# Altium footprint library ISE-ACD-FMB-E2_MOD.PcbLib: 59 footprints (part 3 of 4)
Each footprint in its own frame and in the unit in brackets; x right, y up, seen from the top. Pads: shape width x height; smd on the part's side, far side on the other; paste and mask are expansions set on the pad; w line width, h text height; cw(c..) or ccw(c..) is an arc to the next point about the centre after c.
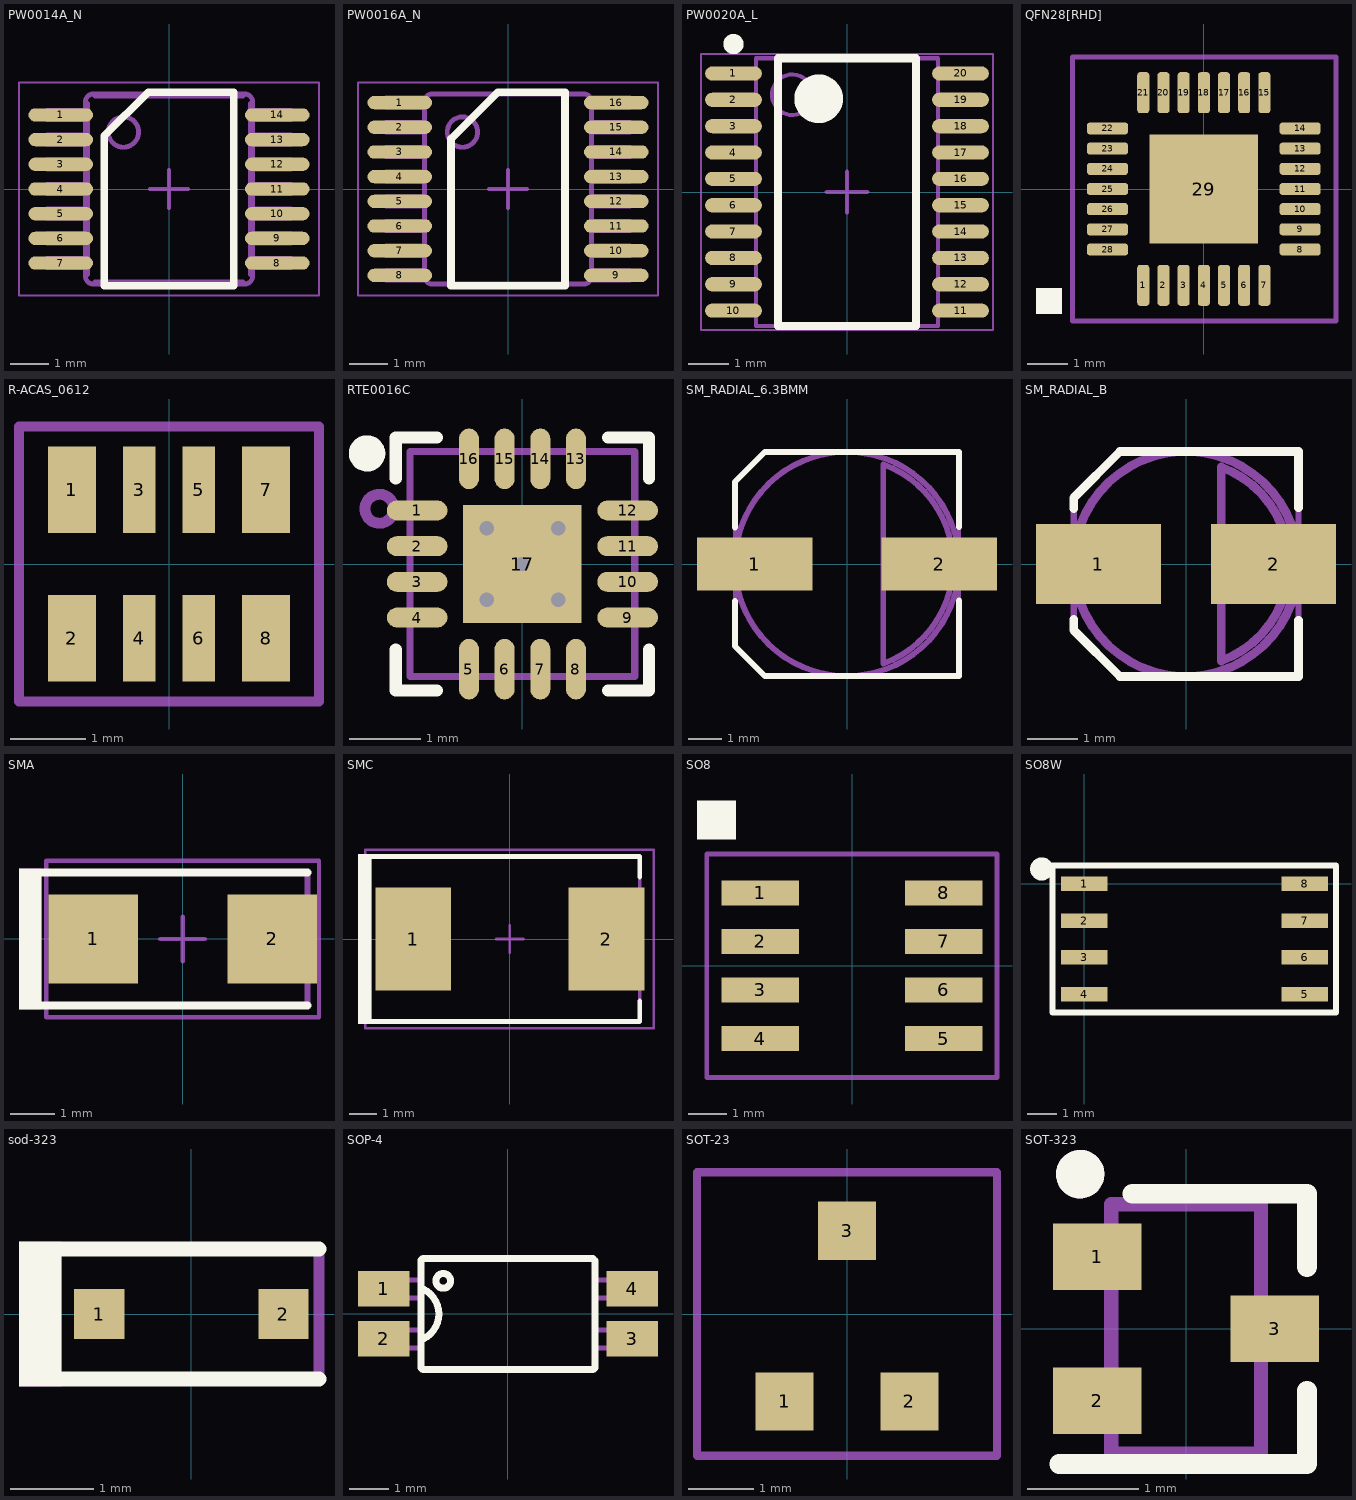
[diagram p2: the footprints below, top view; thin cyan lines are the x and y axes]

## PW0014A_N [mm] "TSOP, 14-Leads, Body 5x4.4mm, Pitch 0.65mm, IPC Medium Density"
height 1.2
pads (14):
  oval 1.7x0.35 smd: 1(-2.85,1.95) 2(-2.85,1.3) 3(-2.85,0.65) 4(-2.85,0) 5(-2.85,-0.65) 6(-2.85,-1.3) 7(-2.85,-1.95) 8(2.85,-1.95) 9(2.85,-1.3) 10(2.85,-0.65) 11(2.85,0) 12(2.85,0.65) 13(2.85,1.3) 14(2.85,1.95)
Top Overlay:
  lines w0.2: -1.7,-2.55 -1.7,1.4 -0.55,2.55 1.7,2.55 1.7,-2.55 -1.7,-2.55
Mechanical 5:
  drawing of 182 lines, arcs and shapes, not listed
  text ".Designator" at 1.219,0.389 h0.91
Mechanical 15:
  lines w0.05: -3.95,-2.8 3.95,-2.8 3.95,2.8 -3.95,2.8 -3.95,-2.8
  lines w0.1: -0.5,0 0.5,0 ; 0,-0.5 0,0.5
3D body: height 0.98, standoff -0.02, extent -3.21,-2.5 3.21,2.5

## PW0016A_N [mm] "TSOP, 16-Leads, Body 5x4.4mm, Pitch 0.65mm, IPC Medium Density"
height 1.2
pads (16):
  oval 1.7x0.35 smd: 1(-2.85,2.275) 2(-2.85,1.625) 3(-2.85,0.975) 4(-2.85,0.325) 5(-2.85,-0.325) 6(-2.85,-0.975) 7(-2.85,-1.625) 8(-2.85,-2.275) 9(2.85,-2.275) 10(2.85,-1.625) 11(2.85,-0.975) 12(2.85,-0.325) 13(2.85,0.325) 14(2.85,0.975) 15(2.85,1.625) 16(2.85,2.275)
Top Overlay:
  lines w0.2: -1.5,-2.55 -1.5,1.325 -0.275,2.55 1.5,2.55 1.5,-2.55 -1.5,-2.55
Mechanical 5:
  drawing of 202 lines, arcs and shapes, not listed
  text ".Designator" at -1.041,-0.432 h0.91
Mechanical 15:
  lines w0.05: -3.95,-2.8 3.95,-2.8 3.95,2.8 -3.95,2.8 -3.95,-2.8
  lines w0.1: -0.5,0 0.5,0 ; 0,-0.5 0,0.5
3D body: height 0.98, standoff -0.02, extent -3.21,-2.5 3.21,2.5

## PW0020A_L [mm] "TSOP, 20-Leads, Body 6.5x4.4mm, Pitch 0.65mm, IPC High Density"
height 1.2
pads (20):
  oval 1.4x0.35 smd: 1(-2.8,2.925) 2(-2.8,2.275) 3(-2.8,1.625) 4(-2.8,0.975) 5(-2.8,0.325) 6(-2.8,-0.325) 7(-2.8,-0.975) 8(-2.8,-1.625) 9(-2.8,-2.275) 10(-2.8,-2.925) 11(2.8,-2.925) 12(2.8,-2.275) 13(2.8,-1.625) 14(2.8,-0.975) 15(2.8,-0.325) 16(2.8,0.325) 17(2.8,0.975) 18(2.8,1.625) 19(2.8,2.275) 20(2.8,2.925)
Top Overlay:
  circle w0.6: c-0.7,2.3 r0.3
  circle w0.25: c-2.8,3.65 r0.125
  lines w0.2: -1.7,-3.3 1.7,-3.3 1.7,3.3 -1.7,3.3 -1.7,-3.3
Mechanical 5:
  circle w0.1: c-1.35,2.4 r0.5
  lines w0.1: -2.25,-3.3 2.25,-3.3 2.25,3.3 -2.25,3.3 -2.25,-3.3
  text ".Designator" at -1.321,-0.508 h0.91
Mechanical 15:
  lines w0.05: -3.6,-3.4 3.6,-3.4 3.6,3.4 -3.6,3.4 -3.6,-3.4
  lines w0.1: -0.5,0 0.5,0 ; 0,-0.5 0,0.5
3D body: height 1.2, standoff 0.05, extent -2.25,-3.3 2.25,3.3

## QFN28[RHD] [mil]
pads (29):
  rrect50% 11.8x40 smd mask+2: 1(-59.1,-94) 2(-39.4,-94) 3(-19.7,-94) 4(0,-94) 5(19.7,-94) 6(39.4,-94) 7(59.1,-94) 15(59.1,94) 16(39.4,94) 17(19.7,94) 18(0,94) 19(-19.7,94) 20(-39.4,94) 21(-59.1,94)
  rrect50% 40x11.8 smd mask+2: 8(94,-59.1) 9(94,-39.4) 10(94,-19.7) 11(94,0) 12(94,19.7) 13(94,39.4) 14(94,59.1) 22(-94,59.1) 23(-94,39.4) 24(-94,19.7) 25(-94,0) 26(-94,-19.7) 27(-94,-39.4) 28(-94,-59.1)
  rect 106x106 smd mask+2: 29(0,0)
Top Overlay:
  region: -163.8,-96.8 -138.8,-96.8 -138.8,-121.8 -163.8,-121.8
Mechanical 5:
  lines w5: -128,-129 -128,129 129,129 129,-129 -128,-129
  text "*" at -100,-130 h40
  text ".Designator" at 14,-28 h36

## R-ACAS_0612 [mil]
pads (8):
  rect 25x45 smd mask+2: 1(-50.5,38.5) 2(-50.5,-38.5) 7(50.5,38.5) 8(50.5,-38.5)
  rect 17x45 smd mask+2: 3(-15.5,38.5) 4(-15.5,-38.5) 5(15.5,38.5) 6(15.5,-38.5)
Mechanical 5:
  lines w5: -78,-71.5 -78,71.5 78,71.5 78,-71.5 -78,-71.5
  text ".Designator" at 53.53,20.17 h30

## RTE0016C [mm] "Texas Insturments"
height 0.8
pads (17):
  oval 0.85x0.28 smd mask+0.051: 1(-1.475,0.75) 2(-1.475,0.25) 3(-1.475,-0.25) 4(-1.475,-0.75) 9(1.475,-0.75) 10(1.475,-0.25) 11(1.475,0.25) 12(1.475,0.75)
  oval 0.28x0.85 smd mask+0.051: 5(-0.75,-1.475) 6(-0.25,-1.475) 7(0.25,-1.475) 8(0.75,-1.475) 13(0.75,1.475) 14(0.25,1.475) 15(-0.25,1.475) 16(-0.75,1.475)
  rect 1.66x1.66 smd paste-0.88: 17(0,0)
via -0.5,0.5 diameter 0.508 hole 0.203
via 0.5,0.5 diameter 0.508 hole 0.203
via 0.5,-0.5 diameter 0.508 hole 0.203
via -0.5,-0.5 diameter 0.508 hole 0.203
via 0,0 diameter 0.508 hole 0.203
Top Overlay:
  circle w0.254: c-2.177,1.55 r0.127
  lines w0.17: -1.775,-1.2 -1.775,-1.775 -1.2,-1.775 ; -1.775,1.2 -1.775,1.775 -1.2,1.775 ; 1.2,-1.775 1.775,-1.775 1.775,-1.2 ; 1.2,1.775 1.775,1.775 1.775,1.2
Top Paste:
  rectangle: 0.1,-0.8 0.8,-0.1
  region: -0.1,-0.1 -0.8,-0.1 -0.8,-0.8 -0.1,-0.8
  region: -0.1,0.8 -0.8,0.8 -0.8,0.1 -0.1,0.1
  rectangle: 0.1,0.1 0.8,0.8
Mechanical 5:
  circle w0.152: c-2.005,0.774 r0.203
  lines w0.1: -1.575,-1.575 1.575,-1.575 1.575,1.575 -1.575,1.575 -1.575,-1.575
  text ".Designator" at -1.2,-0.375 h0.91
3D body: height 0.8, standoff 0, extent -1.575,-1.575 1.575,1.575
3D body: height 0.81, standoff 0.7, extent -1.353,0.822 -0.947,1.228

## SM_RADIAL_6.3BMM [mm] "Nichicon 6.3x7.7"
height 8
pads (2):
  rect 3.5x1.6 smd: 1(-2.8,0) 2(2.8,0)
Top Overlay:
  lines w0.178: -3.4,-1.122 -3.4,-2.493 -2.493,-3.4 3.4,-3.4 3.4,-1.112 ; -3.4,1.108 -3.4,2.493 -2.493,3.4 3.4,3.4 3.4,1.118
Mechanical 5:
  lines w0.127: -3.4,-2.493 -2.493,-3.4 3.4,-3.4 3.4,3.4 -2.493,3.4 -3.4,2.493 -3.4,-2.493
  text ".Designator" at -0.533,0.889 h0.91
Mechanical 13:
  circle w0.178: c0,0 r3.4
  lines w0.178: 1.1,-3.022 ccw(c0,0) 1.1,3.022 1.1,-3.022
3D body: height 8, standoff 6, extent 1.1,-3.026 3.227,3.026
3D body: height 8, standoff 1, extent -3.41,-3.41 3.41,3.41
3D body: height 1, standoff 0, extent -3.401,-3.401 3.401,3.401

## SM_RADIAL_B [mm] "4 x 5.8mm:  Panasonic B"
height 6.1
pads (2):
  rect 2.5x1.6 smd: 1(-1.75,0) 2(1.75,0)
Top Overlay:
  lines w0.178: -2.244,-1.113 -2.244,-1.326 -1.32,-2.25 2.25,-2.25 2.25,-1.126 ; -2.244,1.113 -2.244,1.326 -1.32,2.25 2.25,2.25 2.25,1.126
Mechanical 5:
  lines w0.127: -2.244,-1.326 -1.32,-2.25 2.25,-2.25 2.25,2.25 -1.32,2.25 -2.244,1.326 -2.244,-1.326
  text ".Designator" at -1.245,-0.508 h0.91
Mechanical 13:
  circle w0.178: c0,0 r2.25
  lines w0.178: 0.705,-1.937 ccw(c0,0) 0.705,1.937 0.705,-1.937
3D body: height 0.6, standoff 0, extent -2.245,-2.251 2.251,2.251
3D body: height 6.1, standoff 0.6, extent -2.26,-2.26 2.26,2.26
3D body: height 6.1, standoff 6, extent 0.705,-1.941 2.072,1.941

## SMA [mm] "Molded Diode, 2-Leads, Body 4.3x2.6mm, IPC Medium Density, based on OnSemi component dimensions and land pattern"
height 2.27
pads (2):
  rect 2x2 smd: 1(-2,0) 2(2,0)
Top Overlay:
  rectangle: -3.658,-1.575 -3.15,1.575
  lines w0.178: -3.327,-1.486 2.794,-1.486 ; -3.327,1.486 2.794,1.486
Mechanical 5:
  rectangle: -3.658,-1.575 -3.15,1.575
  lines w0.127: -3.327,-1.486 2.794,-1.486 2.794,1.486 -3.327,1.486
  text ".Designator" at 0.923,0.392 h0.76
Mechanical 15:
  lines w0.1: -0.5,0 0.5,0 ; 0,-0.5 0,0.5 ; -3.05,-1.75 -3.05,1.75 3.05,1.75 3.05,-1.75 -3.05,-1.75
3D body: height 2.42, standoff 0.02, extent -2.6,-1.3 2.6,1.3

## SMC [mil] "Molded Diode, 2-Leads, Body 6.9x5.8mm, IPC Medium Density, based on OnSemi component dimensions and land patterns"
height 94.88
pads (2):
  rect 110x150 smd: 1(-140.49,0) 2(140.49,0)
Top Overlay:
  rectangle: -220.98,-123.5 -200.98,123.5
  lines w7: -210,-120 189,-120 189,-90.25 ; -210,120 189,120 189,90.25
Mechanical 5:
  rectangle: -220.98,-123.5 -200.98,123.5
  lines w5: -210,-120 189,-120 189,120 -210,120
  text ".Designator" at -24,31 h36
Mechanical 15:
  lines w3.94: -19.69,0 19.68,0 ; 0,-19.68 0,19.68 ; -210.46,-129.92 -210.46,129.92 209.38,129.92 209.38,-129.92 -210.46,-129.92
3D body: height 91.35, standoff 0.6, extent -156.49,-116.13 156.5,116.15

## SO8 [mil]
pads (8):
  rect 80x26 smd: 1(-95,75) 2(-95,25) 3(-95,-25) 4(-95,-75) 5(94,-75) 6(94,-25) 7(94,25) 8(94,75)
Top Overlay:
  region: -120,130 -120,170 -160,170 -160,130
Mechanical 5:
  lines w5: -150,-115 -150,115 149,115 149,-115 -150,-115
  text "*" at -105,45 h40
  text ".Designator" at -28,-19 h36

## SO8W [mm] "SO8W P 7.62mm X 1.27"
height 2.5
pads (8):
  rect 1.6x0.5 smd: 1(0,0) 2(0,-1.27) 3(0,-2.54) 4(0,-3.81) 5(7.62,-3.81) 6(7.62,-2.54) 7(7.62,-1.27) 8(7.62,0)
Top Overlay:
  circle w0.4: c-1.47,0.516 r0.2
  lines w0.2: -1.1,-4.445 -1.1,0.635 8.7,0.635 8.7,-4.445 -1.1,-4.445

## sod-323 [mm] "NXP recommended land pattern"
height 1.1
pads (2):
  rect 0.6x0.6 smd: 1(-1.1,0) 2(1.1,0)
Top Overlay:
  rectangle: -2.057,-0.864 -1.549,0.864
  lines w0.178: -1.803,-0.775 0.1,-0.775 1.525,-0.775 ; -1.803,0.775 0.1,0.775 1.525,0.775
Mechanical 5:
  rectangle: -2.057,-0.864 -1.549,0.864
  lines w0.127: -1.803,-0.775 0.1,-0.775 1.525,-0.775 1.525,0.775 0.1,0.775 -1.803,0.775
  text ".Designator" at -0.813,-0.406 h0.91
3D body: height 1.1, standoff 0, extent -1.3,-0.675 1.3,0.675

## SOP-4 [mm] "Vishay Half Pitch Mini-Flat Package"
height 2.1
pads (4):
  rect 1.3x0.9 smd: 1(-3.15,0.635) 2(-3.15,-0.635) 3(3.15,-0.635) 4(3.15,0.635)
Top Overlay:
  lines w0.178: -2.161,-0.649 ccw(c-2.459,-0.01) -2.161,0.629 ; 2.15,1.39 -2.15,1.39 ccw(c-2.15,1.34) -2.2,1.34 -2.2,-1.36 ccw(c-2.15,-1.36) -2.15,-1.41 2.15,-1.41 ccw(c2.15,-1.36) 2.2,-1.36 2.2,1.34 ; -1.641,0.643 cw(c-1.641,0.83) -1.641,1.017 cw(c-1.641,0.83) -1.641,0.643
Mechanical 5:
  lines w0.127: -2.2,-0.87 -2.597,-0.87 -2.696,-0.87 -2.877,-0.87 -2.926,-0.87 -3.5,-0.87 -3.5,-0.42 -2.926,-0.42 -2.877,-0.42 -2.696,-0.42 -2.597,-0.42 -2.2,-0.42 ; -2.2,0.4 -2.597,0.4 -2.696,0.4 -2.877,0.4 -2.926,0.4 -3.5,0.4 -3.5,0.85 -2.926,0.85 -2.877,0.85 -2.696,0.85 -2.597,0.85 -2.2,0.85 ; -2.161,-0.649 ccw(c-2.459,-0.01) -2.161,0.629 ; -2.077,-0.603 ccw(c-2.459,-0.01) -2.025,-0.566 ; -2.077,0.583 cw(c-2.459,-0.01) -2.025,0.546 ; 2.2,-0.87 2.597,-0.87 2.696,-0.87 2.877,-0.87 2.926,-0.87 3.5,-0.87 3.5,-0.42 2.926,-0.42 2.877,-0.42 2.696,-0.42 2.597,-0.42 2.2,-0.42 ; 2.2,0.4 2.597,0.4 2.696,0.4 2.877,0.4 2.926,0.4 3.5,0.4 3.5,0.85 2.926,0.85 2.877,0.85 2.696,0.85 2.597,0.85 2.2,0.85 ; -2.2,-1.36 ccw(c-2.15,-1.36) -2.15,-1.41 2.15,-1.41 ccw(c2.15,-1.36) 2.2,-1.36 2.2,1.34 ccw(c2.15,1.34) 2.15,1.39 -2.15,1.39 ccw(c-2.15,1.34) -2.2,1.34 -2.2,-1.36 ; -1.641,0.643 ccw(c-1.641,0.83) -1.641,1.017 ccw(c-1.641,0.83) -1.641,0.643
  text ".Designator" at -1.041,-0.483 h0.91
3D body: height 2.12, standoff 0.02, extent -3.5,-1.4 3.5,1.4

## SOT-23 [mil]
pads (3):
  rect 35x35 smd: 1(-37.5,-52.5) 2(37.5,-52.5) 3(0,50)
Mechanical 5:
  lines w5: -90,-85 -90,85 90,85 90,-85 -75,-85 -90,-85
  text ".Designator" at 19,-49 h36

## SOT-323 [mm] "Zetex recommended land pattern.  March 2007"
height 1.1
pads (3):
  rect 0.8x0.6 smd: 1(-0.8,0.65) 2(-0.8,-0.65) 3(0.8,0)
Top Overlay:
  circle w0.254: c-0.955,1.397 r0.092
  lines w0.178: -1.143,-1.219 1.092,-1.219 1.092,-0.559 ; -0.483,1.219 1.092,1.219 1.092,0.559
Mechanical 5:
  circle w0.254: c-0.955,1.397 r0.092
  lines w0.127: -1.125,-0.8 -1.125,-0.5 -0.975,-0.5 -0.935,-0.5 -0.884,-0.5 -0.725,-0.5 -0.675,-0.5 -0.675,-0.8 -0.725,-0.8 -0.884,-0.8 -0.935,-0.8 -0.975,-0.8 -1.125,-0.8 ; -1.125,0.5 -1.125,0.8 -0.975,0.8 -0.935,0.8 -0.884,0.8 -0.725,0.8 -0.675,0.8 -0.675,0.5 -0.725,0.5 -0.884,0.5 -0.935,0.5 -0.975,0.5 -1.125,0.5 ; -0.675,-1.125 -0.675,1.125 0.675,1.125 0.675,-1.125 -0.675,-1.125 ; 0.675,-0.15 0.725,-0.15 0.884,-0.15 0.935,-0.15 0.975,-0.15 1.125,-0.15 1.125,0.15 0.975,0.15 0.935,0.15 0.884,0.15 0.725,0.15 0.675,0.15 0.675,-0.15
  text ".Designator" at -0.369,1.321 h0.76
3D body: height 1.13, standoff 0.02, extent -1.125,-1.125 1.125,1.125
